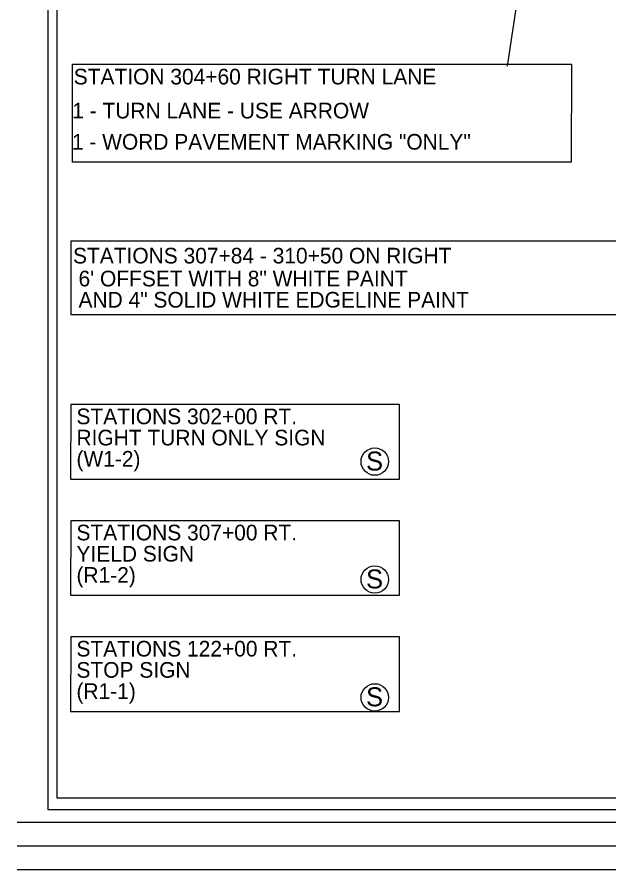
# Model space of a CAD drawing. Extents: x 11779 to 13421, y 9945 to 11090.
# Drawn here: x 11784 to 12270, y 9945 to 10646 of the extents above; entities that cross this region are included whole.
import ezdxf

# ---------------------------------------------------------------- set-up
doc = ezdxf.new("R2010")
doc.units = 0
doc.layers.add('Default', color=7, linetype='Continuous')
doc.layers.add('R_Horz Alg Annot', color=7, linetype='Continuous')

msp = doc.modelspace()

# ---------------------------------------------------------------- linework, layer by layer
at = {"layer": 'Default'}
for p, q in [((11816.83, 10003.88), (11816.83, 11031.1)), ((12209.35, 10752.68), (12186.7, 10605.87)), ((13397.74, 10003.88), (11816.83, 10003.88)), ((11783.99, 9984.17), (13420.77, 9984.17)), ((11783.99, 9964.48), (13420.77, 9964.48)), ((13420.77, 9944.79), (11783.99, 9944.79))]:
    msp.add_line(p, q, dxfattribs=at)
for points in [[(11809.67, 11038.21), (13405.96, 11038.21), (13405.96, 9994.1), (11809.67, 9994.1)], [(11829.56, 10607.4), (12239.56, 10607.4), (12239.48, 10526.83), (11829.62, 10526.83)]]:
    msp.add_lwpolyline(points, close=True, dxfattribs=at)
for points in [[(11828.15, 10462.01), (11828.09, 10401.58), (12305.91, 10401.58), (12305.97, 10462.01), (11828.08, 10462.01)], [(11828.05, 10327.44), (11827.87, 10266.18), (12098.3, 10266.18), (12098.3, 10327.44), (11828.05, 10327.44)], [(11828.05, 10231.92), (11827.87, 10170.66), (12098.3, 10170.66), (12098.3, 10231.92), (11828.05, 10231.92)], [(11828.05, 10136.4), (11827.87, 10075.14), (12098.3, 10075.14), (12098.3, 10136.4), (11828.05, 10136.4)]]:
    msp.add_lwpolyline(points, dxfattribs=at)
for centre in [(12077.95, 10280.59), (12077.95, 10183.64), (12077.95, 10086.7)]:
    msp.add_circle(centre, 11.25, dxfattribs=at)

# ---------------------------------------------------------------- texts
at = {"layer": 'R_Horz Alg Annot'}
for s, height, p in [('STATION 304+60 RIGHT TURN LANE', 12.8746, (11830.58, 10590.77)), ('1 - TURN LANE - USE ARROW', 12.8746, (11829.32, 10562.82)), ('1 - WORD PAVEMENT MARKING "ONLY"', 12.8746, (11829.06, 10537.15)), ('STATIONS 307+84 - 310+50 ON RIGHT', 12.8746, (11829.98, 10443.53)), ('6\' OFFSET WITH 8" WHITE PAINT', 12.8746, (11834.5, 10424.7)), ('AND 4" SOLID WHITE EDGELINE PAINT', 12.8746, (11834.5, 10407.26)), ('STATIONS 302+00 RT.', 12.8746, (11832.81, 10311.34)), ('RIGHT TURN ONLY SIGN', 12.8746, (11832.81, 10293.9)), ('(W1-2)', 12.875, (11832.81, 10276.46)), ('S', 15.62, (12070.86, 10273.23)), ('STATIONS 307+00 RT.', 12.8746, (11832.81, 10215.82)), ('YIELD SIGN', 12.875, (11832.81, 10198.38)), ('(R1-2)', 12.875, (11832.81, 10180.94)), ('S', 15.62, (12070.86, 10176.29)), ('STATIONS 122+00 RT.', 12.8746, (11832.81, 10120.3)), ('STOP SIGN', 12.875, (11832.81, 10102.86)), ('(R1-1)', 12.875, (11832.81, 10085.42)), ('S', 15.62, (12070.86, 10079.35))]:
    msp.add_text(s, height=height, dxfattribs=at).set_placement(p)

doc.saveas('drawing.dxf')
